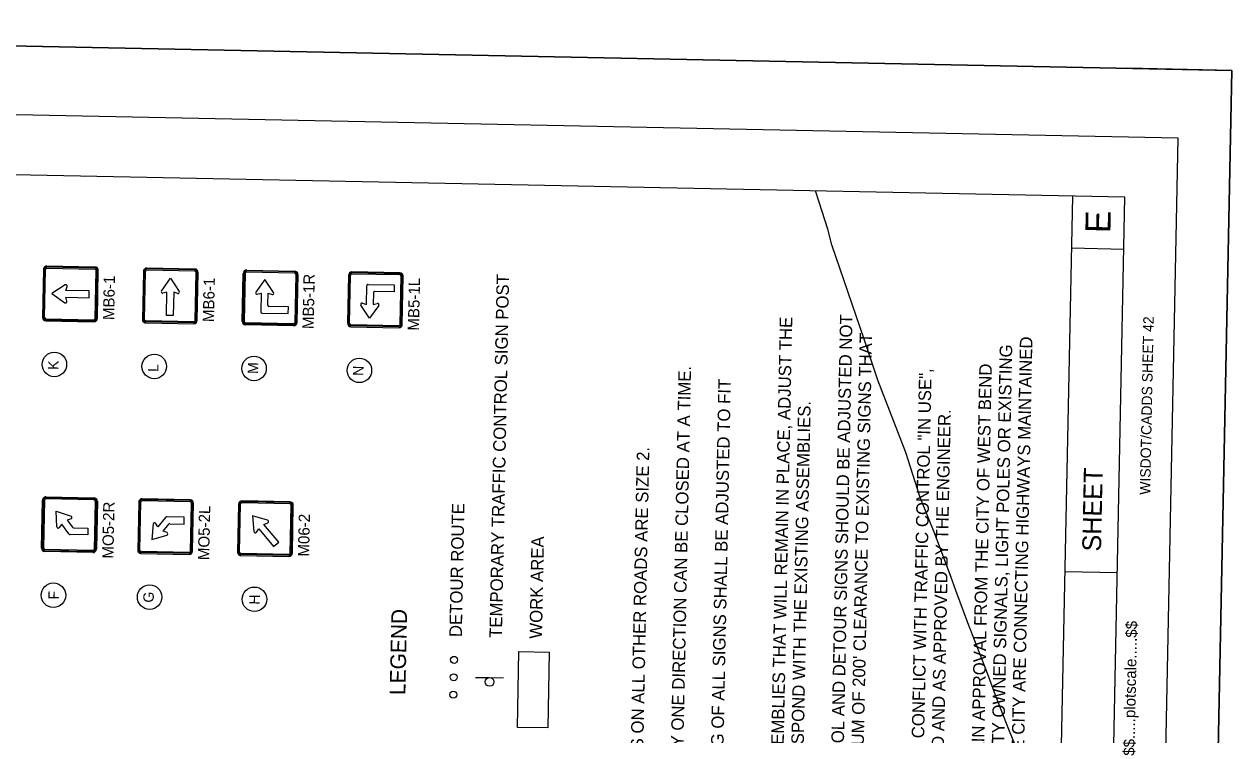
# Model space of a CAD drawing. Extents: x 311409 to 379449, y 121539 to 224848.
# Drawn here: x 344745 to 379449, y 204421 to 224848 of the extents above; entities that cross this region are included whole.
import ezdxf

# ---------------------------------------------------------------- set-up
doc = ezdxf.new("R2010")
doc.units = 0
for name, color, linetype in [('CA-TEXT', 7, 'Continuous'), ('CE-TOPO-CONC-SLAB', 7, 'Continuous'), ('Level 1', 7, 'Continuous'), ('P_RDWY_Text', 7, 'Continuous'), ('P_SGN_Cell', 7, 'Continuous'), ('P_TC', 7, 'Continuous'), ('PLT_Sheet_Border', 7, 'Continuous'), ('PLT_Sheet_Info', 7, 'Continuous'), ('SIGNS-POLES', 7, 'Continuous')]:
    doc.layers.add(name, color=color, linetype=linetype)

msp = doc.modelspace()

# ---------------------------------------------------------------- linework, layer by layer
at = {"layer": 'CA-TEXT'}
for centre in [(345614, 215067), (348483, 215009), (351351, 214952), (354378, 214897), (345586, 208434), (348349, 208379), (351363, 208318)]:
    msp.add_circle(centre, 352, dxfattribs=at)
at = {"layer": 'CE-TOPO-CONC-SLAB'}
for centre in [(357098, 206576), (357088, 206076), (357078, 205576)]:
    msp.add_circle(centre, 100, dxfattribs=at)
at = {"layer": 'Level 1'}
for points in [[(370489, 211247), (370080, 212533), (369274, 214615), (368884, 215794), (367958, 218502), (367837, 218953), (367594, 219730), (367482, 220054)], [(374168, 201575), (373841, 202548), (373499, 203451), (373059, 204530), (372716, 205409), (372399, 206261), (371861, 207641), (371520, 208569), (371373, 208971), (370934, 210150), (370489, 211247)]]:
    msp.add_lwpolyline(points, dxfattribs=at)
at = {"layer": 'P_RDWY_Text'}
msp.add_lwpolyline([(311409, 122868), (313463, 224848), (379449, 223519), (377396, 121539)], close=True, dxfattribs=at)
at = {"layer": 'P_SGN_Cell'}
for p, q in [((345301, 217798), (345273, 216421)), ((345299, 216420), (345327, 217798)), ((345332, 216419), (345360, 217797)), ((345400, 217836), (346778, 217808)), ((346779, 217867), (345401, 217895)), ((345401, 217869), (346779, 217841)), ((346789, 216390), (346817, 217768)), ((346822, 216389), (346849, 217767)), ((346848, 216389), (346876, 217767)), ((348170, 217741), (348142, 216363)), ((348168, 216362), (348196, 217740)), ((348201, 216362), (348229, 217739)), ((349647, 217783), (348269, 217811)), ((349647, 217750), (348269, 217778)), ((349648, 217809), (348270, 217837)), ((349658, 216332), (349685, 217710)), ((349690, 216332), (349718, 217709)), ((349717, 216331), (349744, 217709)), ((351010, 216305), (351038, 217683)), ((351064, 217682), (351037, 216305)), ((351097, 217682), (351070, 216304)), ((352515, 217693), (351137, 217720)), ((352516, 217725), (351138, 217753)), ((351139, 217779), (352516, 217752)), ((352554, 217652), (352526, 216275)), ((352587, 217652), (352559, 216274)), ((352613, 217651), (352585, 216273)), ((354064, 217628), (354037, 216251)), ((354063, 216250), (354091, 217628)), ((354096, 216249), (354124, 217627)), ((355542, 217671), (354164, 217699)), ((355542, 217638), (354164, 217666)), ((355543, 217697), (354165, 217725)), ((345919, 217352), (345543, 217104)), ((345942, 217195), (345979, 217307)), ((348690, 217177), (348953, 217543)), ((348953, 217543), (349201, 217166)), ((351665, 217513), (351402, 217147)), ((351913, 217136), (351665, 217513)), ((354579, 216794), (354590, 217329)), ((354630, 217368), (355378, 217352)), ((355378, 217352), (355374, 217156)), ((355552, 216220), (355580, 217598)), ((355585, 216219), (355613, 217597)), ((355611, 216219), (355639, 217597)), ((345543, 217104), (345909, 216841)), ((345970, 216884), (345938, 216998)), ((345938, 216998), (346610, 216984)), ((346614, 217181), (345942, 217195)), ((346610, 216984), (346614, 217181)), ((348847, 217148), (348733, 217116)), ((348833, 216475), (348847, 217148)), ((349044, 217144), (349030, 216471)), ((349156, 217107), (349044, 217144)), ((351445, 217086), (351559, 217118)), ((351559, 217118), (351548, 216583)), ((351748, 216769), (351755, 217114)), ((351755, 217114), (351868, 217077)), ((354783, 217135), (354776, 216790)), ((355374, 217156), (354817, 217167)), ((352338, 216725), (351781, 216736)), ((352334, 216528), (352338, 216725)), ((354670, 216395), (354422, 216772)), ((354467, 216831), (354579, 216794)), ((354933, 216762), (354670, 216395)), ((354776, 216790), (354890, 216822)), ((345370, 216346), (346748, 216319)), ((345370, 216320), (346748, 216292)), ((345371, 216379), (346749, 216352)), ((348238, 216262), (349616, 216235)), ((349617, 216261), (348239, 216289)), ((349617, 216294), (348240, 216321)), ((349030, 216471), (348833, 216475)), ((352485, 216203), (351107, 216231)), ((352486, 216236), (351108, 216264)), ((351586, 216543), (352334, 216528)), ((352485, 216177), (351107, 216205)), ((354133, 216150), (355511, 216122)), ((355512, 216181), (354134, 216209)), ((355512, 216149), (354134, 216176)), ((345245, 209788), (345273, 211166)), ((345299, 211165), (345271, 209787)), ((345332, 211164), (345304, 209787)), ((346750, 211175), (345372, 211203)), ((345373, 211262), (346751, 211234)), ((346751, 211208), (345373, 211236)), ((346789, 211135), (346761, 209757)), ((346821, 211134), (346794, 209757)), ((346848, 211134), (346820, 209756)), ((348036, 211110), (348008, 209732)), ((348035, 209732), (348062, 211109)), ((348067, 209731), (348095, 211109)), ((349513, 211120), (348135, 211147)), ((349514, 211179), (348136, 211206)), ((349514, 211152), (348136, 211180)), ((349524, 209702), (349552, 211079)), ((349557, 209701), (349584, 211079)), ((349583, 209700), (349611, 211078)), ((350905, 211052), (350877, 209674)), ((350903, 209674), (350931, 211052)), ((350936, 209673), (350964, 211051)), ((352382, 211062), (351004, 211090)), ((352383, 211121), (351005, 211149)), ((352382, 211095), (351005, 211122)), ((352393, 209644), (352420, 211022)), ((352425, 209643), (352453, 211021)), ((352452, 209643), (352479, 211021)), ((345684, 210399), (345666, 210849)), ((345666, 210849), (346093, 210705)), ((348806, 210670), (348588, 210403)), ((349347, 210677), (348842, 210687)), ((349343, 210480), (349347, 210677)), ((351737, 210592), (351305, 210713)), ((351305, 210713), (351346, 210264)), ((345825, 210472), (345755, 210377)), ((346032, 210197), (345825, 210472)), ((346094, 210631), (345983, 210590)), ((345983, 210590), (346136, 210386)), ((346161, 210373), (346576, 210365)), ((346576, 210365), (346572, 210168)), ((348450, 210482), (348414, 210033)), ((348588, 210403), (348522, 210501)), ((348741, 210278), (348902, 210476)), ((348928, 210488), (349343, 210480)), ((351419, 210246), (351484, 210345)), ((351484, 210345), (351909, 209836)), ((351635, 210471), (351744, 210517)), ((352060, 209962), (351635, 210471)), ((346572, 210168), (346068, 210178)), ((348414, 210033), (348846, 210159)), ((348850, 210233), (348741, 210278)), ((346720, 209686), (345342, 209714)), ((346720, 209660), (345342, 209687)), ((346721, 209719), (345343, 209746)), ((349483, 209630), (348105, 209658)), ((348105, 209632), (349483, 209604)), ((349484, 209663), (348106, 209691)), ((352352, 209605), (350975, 209633)), ((351909, 209836), (352060, 209962)), ((350973, 209574), (352351, 209546)), ((352352, 209572), (350974, 209600))]:
    msp.add_line(p, q, dxfattribs=at)
for centre, radius, start, end in [((345399, 217796), 98.4, 88.8462, 178.8462), ((345399, 217796), 98.4, 149.4497, 178.8462), ((345399, 217796), 72.2, 88.8462, 178.8462), ((345399, 217796), 39.4, 88.8462, 178.8462), ((346777, 217769), 39.4, 358.8462, 88.8462), ((346777, 217769), 98.4, 358.8462, 88.8462), ((346777, 217769), 72.2, 358.8462, 88.8462), ((348268, 217739), 98.4, 88.8462, 178.8462), ((348268, 217739), 72.2, 88.8462, 178.8462), ((348268, 217739), 39.4, 88.8462, 178.8462), ((349646, 217711), 72.2, 358.8462, 88.8462), ((349646, 217711), 39.4, 358.8462, 88.8462), ((349646, 217711), 98.4, 358.8462, 88.8462), ((351137, 217681), 98.4, 88.8462, 178.8462), ((351137, 217681), 72.2, 88.8462, 178.8462), ((351137, 217681), 39.4, 88.8462, 178.8462), ((352515, 217653), 39.4, 358.8462, 88.8462), ((352515, 217653), 98.4, 358.8462, 88.8462), ((352515, 217653), 72.2, 358.8462, 88.8462), ((354163, 217626), 98.4, 88.8462, 178.8462), ((354163, 217626), 72.2, 88.8462, 178.8462), ((354163, 217626), 39.4, 88.8462, 178.8462), ((355541, 217599), 39.4, 358.8462, 88.8462), ((355541, 217599), 72.2, 358.8462, 88.8462), ((355541, 217599), 98.4, 358.8462, 88.8462), ((345941, 217320), 39.4, 342.0436, 123.3759), ((354629, 217328), 39.4, 88.8462, 178.8462), ((348722, 217154), 39.4, 144.3166, 285.6488), ((349168, 217145), 39.4, 252.0436, 33.3759), ((351434, 217124), 39.4, 144.3166, 285.6488), ((351880, 217115), 39.4, 252.0436, 33.3759), ((354816, 217134), 32.8, 88.8462, 178.8462), ((345932, 216873), 39.4, 234.3166, 15.6488), ((351587, 216582), 39.4, 178.8462, 268.8462), ((351781, 216769), 32.8, 178.8462, 268.8462), ((354455, 216793), 39.4, 72.0436, 213.3759), ((354901, 216784), 39.4, 324.3166, 105.6488), ((345372, 216419), 98.4, 178.8462, 268.8462), ((345372, 216419), 72.2, 178.8462, 268.8462), ((345372, 216419), 39.4, 178.8462, 268.8462), ((346749, 216391), 72.2, 268.8462, 358.8462), ((346749, 216391), 98.4, 268.8462, 358.8462), ((346749, 216391), 39.4, 268.8462, 358.8462), ((348240, 216361), 98.4, 178.8462, 268.8462), ((348240, 216361), 72.2, 178.8462, 268.8462), ((348240, 216361), 98.4, 239.4497, 268.8462), ((348240, 216361), 39.4, 178.8462, 268.8462), ((349618, 216333), 98.4, 268.8462, 358.8462), ((349618, 216333), 72.2, 268.8462, 358.8462), ((349618, 216333), 39.4, 268.8462, 358.8462), ((351109, 216303), 98.4, 178.8462, 268.8462), ((351109, 216303), 72.2, 178.8462, 268.8462), ((351109, 216303), 39.4, 178.8462, 268.8462), ((352487, 216275), 72.2, 268.8462, 358.8462), ((352487, 216275), 98.4, 268.8462, 358.8462), ((352487, 216275), 39.4, 268.8462, 358.8462), ((354135, 216249), 98.4, 178.8462, 268.8462), ((354135, 216249), 72.2, 178.8462, 268.8462), ((354135, 216249), 39.4, 178.8462, 268.8462), ((355513, 216221), 98.4, 268.8462, 358.8462), ((355513, 216221), 39.4, 268.8462, 358.8462), ((355513, 216221), 72.2, 268.8462, 358.8462), ((345371, 211164), 98.4, 88.8462, 178.8462), ((345371, 211164), 98.4, 144.5056, 178.8462), ((345371, 211164), 72.2, 88.8462, 178.8462), ((345371, 211164), 98.4, 88.8462, 113.5578), ((345371, 211164), 39.4, 88.8462, 178.8462), ((346749, 211136), 39.4, 358.8462, 88.8462), ((346749, 211136), 98.4, 358.8462, 88.8462), ((346749, 211136), 72.2, 358.8462, 88.8462), ((348134, 211108), 98.4, 88.8462, 178.8462), ((348134, 211108), 72.2, 88.8462, 178.8462), ((348134, 211108), 39.4, 88.8462, 178.8462), ((349512, 211080), 39.4, 358.8462, 88.8462), ((349512, 211080), 98.4, 358.8462, 88.8462), ((349512, 211080), 72.2, 358.8462, 88.8462), ((351003, 211050), 98.4, 88.8462, 178.8462), ((351003, 211050), 72.2, 88.8462, 178.8462), ((351003, 211050), 39.4, 88.8462, 178.8462), ((352381, 211023), 72.2, 358.8462, 88.8462), ((352381, 211023), 39.4, 358.8462, 88.8462), ((352381, 211023), 98.4, 358.8462, 88.8462), ((346080, 210668), 39.4, 290.0436, 71.3759), ((348841, 210641), 45.9, 88.8462, 140.8466), ((345723, 210400), 39.4, 182.3166, 323.6488), ((346162, 210406), 32.8, 216.8461, 268.8462), ((348489, 210479), 39.4, 34.0436, 175.3759), ((348927, 210455), 32.8, 88.8462, 140.8463), ((351728, 210554), 39.4, 292.7827, 77.9371), ((346069, 210224), 45.9, 216.8459, 268.8462), ((348835, 210197), 39.4, 286.3166, 67.6488), ((351386, 210268), 39.4, 185.2961, 326.6328), ((345344, 209786), 98.4, 178.8462, 268.8462), ((345344, 209786), 72.2, 178.8462, 268.8462), ((345344, 209786), 39.4, 178.8462, 268.8462), ((346721, 209758), 72.2, 268.8462, 358.8462), ((346721, 209758), 98.4, 268.8462, 358.8462), ((346721, 209758), 39.4, 268.8462, 358.8462), ((348107, 209730), 98.4, 178.8462, 268.8462), ((348107, 209730), 98.4, 178.8462, 213.1868), ((348107, 209730), 72.2, 178.8462, 268.8462), ((348107, 209730), 98.4, 244.1347, 268.8462), ((348107, 209730), 39.4, 178.8462, 268.8462), ((349485, 209702), 72.2, 268.8462, 358.8462), ((349485, 209702), 98.4, 268.8462, 358.8462), ((349485, 209702), 39.4, 268.8462, 358.8462), ((350975, 209672), 98.4, 178.8462, 213.1868), ((350975, 209672), 98.4, 178.8462, 268.8462), ((350975, 209672), 72.2, 178.8462, 268.8462), ((350975, 209672), 39.4, 178.8462, 268.8462), ((352353, 209645), 98.4, 268.8462, 358.8462), ((352353, 209645), 39.4, 268.8462, 358.8462), ((352353, 209645), 72.2, 268.8462, 358.8462), ((350975, 209672), 98.4, 244.1347, 268.8462)]:
    msp.add_arc(centre, radius, start, end, dxfattribs=at)
at = {"layer": 'P_TC'}
msp.add_lwpolyline([(358920, 204635), (358964, 206817), (359834, 206799), (359790, 204618)], close=True, dxfattribs=at)
at = {"layer": 'PLT_Sheet_Border'}
for points in [[(377396, 121539), (379449, 223519), (313463, 224848), (311409, 122868)], [(375910, 122290), (377910, 221569), (314923, 222838), (312923, 123558)]]:
    msp.add_lwpolyline(points, close=True, dxfattribs=at)
at = {"layer": 'PLT_Sheet_Info'}
for p, q in [((379449, 223519), (376450, 223579)), ((379389, 220519), (379449, 223519)), ((376375, 219875), (316388, 221083)), ((372973, 125424), (374876, 219905)), ((374473, 125394), (376375, 219875)), ((376345, 218375), (374846, 218405)), ((376158, 209077), (374658, 209107))]:
    msp.add_line(p, q, dxfattribs=at)
at = {"layer": 'SIGNS-POLES'}
for p, q in [((357710, 206071), (358115, 206068)), ((358118, 206065), (358523, 206060))]:
    msp.add_line(p, q, dxfattribs=at)
msp.add_circle((358121, 205941), 125, dxfattribs=at)

# ---------------------------------------------------------------- texts
at = {"layer": 'CA-TEXT'}
for s, height, rotation, p in [('TEMPORARY TRAFFIC CONTROL SIGN POST', 360, 88.8468, (358473, 207204)), ('IF THERE ARE EXISTING ROUTE MARKER ASSEMBLIES THAT WILL REMAIN IN PLACE, ADJUST THE', 360, 88.8462, (366354, 193328)), ('THE SPACING BETWEEN THE TRAFFIC CONTROL AND DETOUR SIGNS SHOULD BE ADJUSTED NOT', 360, 88.8462, (368082, 193293)), ("TO CONFLICT WITH AND TO PROVIDE A MINIMUM OF 200' CLEARANCE TO EXISTING SIGNS THAT", 360, 88.8462, (368657, 193282)), ('PRIOR TO PLACING ANY DETOUR SIGNS ON CITY OWNED SIGNALS, LIGHT POLES OR EXISTING', 360, 88.8462, (372689, 193201)), ('SIGN POSTS.  STH 33 AND STH 144 WITHIN THE CITY ARE CONNECTING HIGHWAYS MAINTAINED ', 360, 88.8462, (373264, 193189)), ('K', 300, 88.8468, (345731, 214908)), ('L', 300, 88.8468, (348600, 214850)), ('M', 300, 88.8468, (351468, 214792)), ('N', 300, 88.8468, (354494, 214737)), ('NB AND SB CLOSURES ARE SHOWN BUT ONLY ONE DIRECTION CAN BE CLOSED AT A TIME.', 360, 88.8462, (363474, 193386)), ('ANY SIGNS TEMPORARY OR EXISTING, WHICH CONFLICT WITH TRAFFIC CONTROL "IN USE",', 360, 88.8462, (370385, 193247)), ('CONTRACTOR SHALL COORDINATE AND OBTAIN APPROVAL FROM THE CITY OF WEST BEND', 360, 88.8462, (372113, 193212)), ('THE EXACT NUMBER, LOCATION AND SPACING OF ALL SIGNS SHALL BE ADJUSTED TO FIT', 360, 88.8462, (364626, 193363)), ('LOCATION OF THE DETOUR SIGNS TO CORRESPOND WITH THE EXISTING ASSEMBLIES. ', 360, 88.8462, (366930, 193317)), ('SHALL BE REMOVED OR COVERED AS NEEDED AND AS APPROVED BY THE ENGINEER.', 360, 88.8462, (370961, 193235)), ('SIGNS ON I-41 AND USH 45 ARE SIZE 3.  SIGNS ON ALL OTHER ROADS ARE SIZE 2.', 360, 88.8462, (362323, 193409)), ('DETOUR ROUTE', 360, 88.8468, (357321, 207227)), ('WORK AREA', 360, 88.8468, (359624, 207181)), ('F', 300, 88.8468, (345740, 208310)), ('G', 300, 88.8468, (348466, 208219)), ('H', 300, 88.8468, (351515, 208161)), ('LEGEND', 450, 88.8468, (355699, 205561))]:
    msp.add_text(s, height=height, rotation=rotation, dxfattribs=at).set_placement(p)
at = {"layer": 'P_SGN_Cell'}
for s, p in [('MB5-1R', (353065, 216081)), ('MB6-1', (347331, 216340)), ('MB6-1', (350200, 216282)), ('MB5-1L', (356092, 216036)), ('MO5-2R', (347310, 209484)), ('MO5-2L', (350062, 209439)), ('M06-2', (352934, 209542))]:
    msp.add_text(s, height=324, rotation=88.8462, dxfattribs=at).set_placement(p)
at = {"layer": 'PLT_Sheet_Info'}
for s, height, p in [('E', 720, (375959, 218839)), ('WISDOT/CADDS SHEET 42', 300, (377103, 211320)), ('SHEET ', 540, (375690, 209687)), ('$$.....plotscale.....$$', 324, (376652, 203816))]:
    msp.add_text(s, height=height, rotation=88.8462, dxfattribs=at).set_placement(p)

doc.saveas('drawing.dxf')
